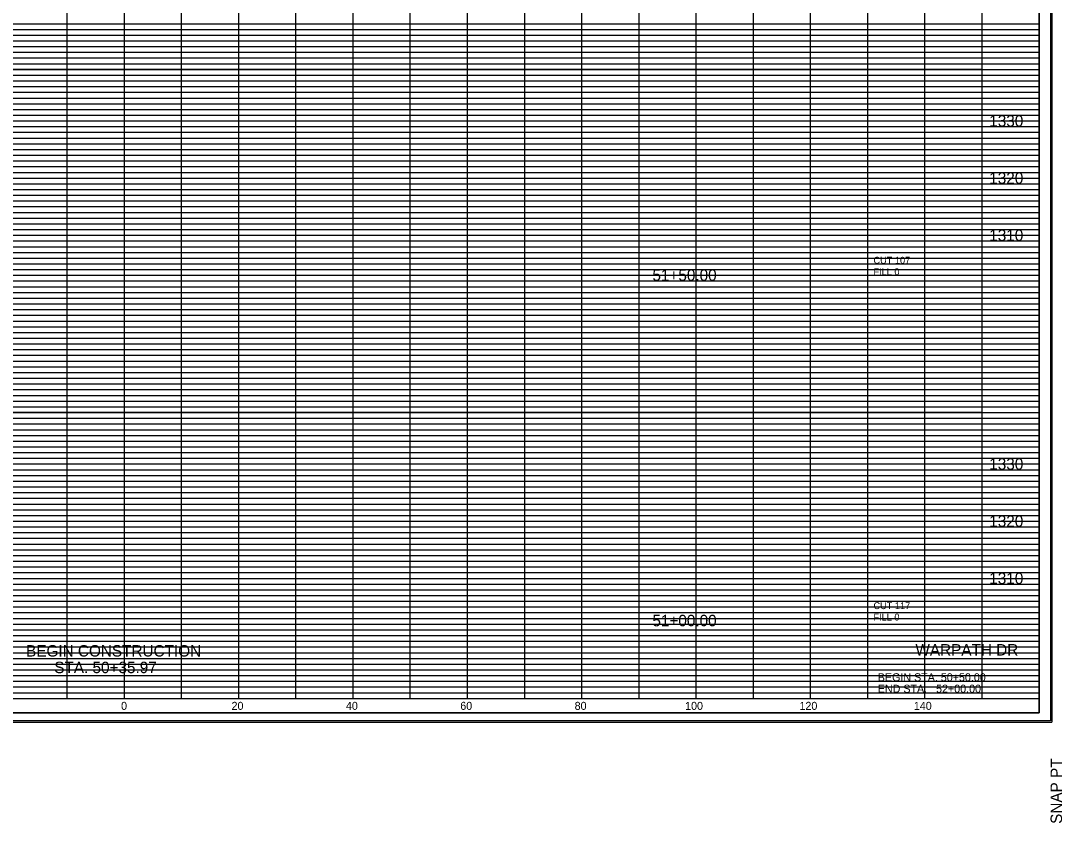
# Model space of a CAD drawing. Extents: x 130 to 1324, y -58 to 2657.
# Drawn here: x 1141.9 to 1324, y 978.2 to 1118.5 of the extents above; entities that cross this region are included whole.
import ezdxf

# ---------------------------------------------------------------- set-up
doc = ezdxf.new("R2010")
doc.units = 0
for name, color, linetype in [('DESIGN - SCRATCH - User 2', 7, 'Continuous'), ('DESIGN - SHEET - Corner Text', 7, 'Continuous'), ('DESIGN - SHEET - Light Grid', 7, 'Continuous'), ('DESIGN - SHEET - Linework', 7, 'Continuous'), ('DESIGN - SHEET - Plot Shape', 7, 'Continuous'), ('DESIGN - TYPICAL - Finished Grade and Subgrade', 7, 'Continuous'), ('DESIGN - TYPICAL - Text', 7, 'Continuous')]:
    doc.layers.add(name, color=color, linetype=linetype)

# ---------------------------------------------------------------- blocks, each defined once
blk = doc.blocks.new('XSTSHT')
at = {"layer": 'DESIGN - SHEET - Light Grid'}
for p, q in [((8, 11.8), (16, 11.8)), ((8, 11.7), (16, 11.7)), ((16, 11.8), (24, 11.8)), ((16, 11.7), (24, 11.7)), ((24, 11.8), (32, 11.8)), ((24, 11.7), (32, 11.7)), ((8, 11.6), (16, 11.6)), ((8, 11.5), (16, 11.5)), ((16, 11.6), (24, 11.6)), ((16, 11.5), (24, 11.5)), ((24, 11.6), (32, 11.6)), ((24, 11.5), (32, 11.5)), ((8, 11.4), (16, 11.4)), ((8, 11.3), (16, 11.3)), ((16, 11.4), (24, 11.4)), ((16, 11.3), (24, 11.3)), ((24, 11.4), (32, 11.4)), ((24, 11.3), (32, 11.3)), ((8, 11.2), (16, 11.2)), ((16, 11.2), (24, 11.2)), ((24, 11.2), (32, 11.2)), ((8, 11.1), (16, 11.1)), ((16, 11.1), (24, 11.1)), ((24, 11.1), (32, 11.1)), ((8, 10.9), (16, 10.9)), ((8, 10.8), (16, 10.8)), ((16, 10.9), (24, 10.9)), ((16, 10.8), (24, 10.8)), ((24, 10.9), (32, 10.9)), ((24, 10.8), (32, 10.8)), ((8, 10.7), (16, 10.7)), ((8, 10.6), (16, 10.6)), ((16, 10.7), (24, 10.7)), ((16, 10.6), (24, 10.6)), ((24, 10.7), (32, 10.7)), ((24, 10.6), (32, 10.6)), ((8, 10.5), (16, 10.5)), ((8, 10.4), (16, 10.4)), ((16, 10.5), (24, 10.5)), ((16, 10.4), (24, 10.4)), ((24, 10.5), (32, 10.5)), ((24, 10.4), (32, 10.4)), ((8, 10.3), (16, 10.3)), ((8, 10.2), (16, 10.2)), ((16, 10.3), (24, 10.3)), ((16, 10.2), (24, 10.2)), ((24, 10.3), (32, 10.3)), ((24, 10.2), (32, 10.2)), ((8, 10.1), (16, 10.1)), ((16, 10.1), (24, 10.1)), ((24, 10.1), (32, 10.1)), ((8, 9.9), (16, 9.9)), ((16, 9.9), (24, 9.9)), ((24, 9.9), (32, 9.9)), ((8, 9.8), (16, 9.8)), ((8, 9.7), (16, 9.7)), ((16, 9.8), (24, 9.8)), ((16, 9.7), (24, 9.7)), ((24, 9.8), (32, 9.8)), ((24, 9.7), (32, 9.7)), ((8, 9.6), (16, 9.6)), ((8, 9.5), (16, 9.5)), ((16, 9.6), (24, 9.6)), ((16, 9.5), (24, 9.5)), ((24, 9.6), (32, 9.6)), ((24, 9.5), (32, 9.5)), ((8, 9.4), (16, 9.4)), ((8, 9.3), (16, 9.3)), ((16, 9.4), (24, 9.4)), ((16, 9.3), (24, 9.3)), ((24, 9.4), (32, 9.4)), ((24, 9.3), (32, 9.3)), ((8, 9.2), (16, 9.2)), ((16, 9.2), (24, 9.2)), ((24, 9.2), (32, 9.2)), ((8, 9.1), (16, 9.1)), ((16, 9.1), (24, 9.1)), ((24, 9.1), (32, 9.1)), ((8, 8.9), (16, 8.9)), ((8, 8.8), (16, 8.8)), ((16, 8.9), (24, 8.9)), ((16, 8.8), (24, 8.8)), ((24, 8.9), (32, 8.9)), ((24, 8.8), (32, 8.8)), ((8, 8.7), (16, 8.7)), ((8, 8.6), (16, 8.6)), ((16, 8.7), (24, 8.7)), ((16, 8.6), (24, 8.6)), ((24, 8.7), (32, 8.7)), ((24, 8.6), (32, 8.6)), ((8, 8.5), (16, 8.5)), ((8, 8.4), (16, 8.4)), ((16, 8.5), (24, 8.5)), ((16, 8.4), (24, 8.4)), ((24, 8.5), (32, 8.5)), ((24, 8.4), (32, 8.4)), ((8, 8.3), (16, 8.3)), ((8, 8.2), (16, 8.2)), ((16, 8.3), (24, 8.3)), ((16, 8.2), (24, 8.2)), ((24, 8.3), (32, 8.3)), ((24, 8.2), (32, 8.2)), ((8, 8.1), (16, 8.1)), ((16, 8.1), (24, 8.1)), ((24, 8.1), (32, 8.1)), ((8, 7.9), (16, 7.9)), ((16, 7.9), (24, 7.9)), ((24, 7.9), (32, 7.9)), ((8, 7.8), (16, 7.8)), ((8, 7.7), (16, 7.7)), ((16, 7.8), (24, 7.8)), ((16, 7.7), (24, 7.7)), ((24, 7.8), (32, 7.8)), ((24, 7.7), (32, 7.7)), ((8, 7.6), (16, 7.6)), ((8, 7.5), (16, 7.5)), ((16, 7.6), (24, 7.6)), ((16, 7.5), (24, 7.5)), ((24, 7.6), (32, 7.6)), ((24, 7.5), (32, 7.5)), ((8, 7.4), (16, 7.4)), ((8, 7.3), (16, 7.3)), ((16, 7.4), (24, 7.4)), ((16, 7.3), (24, 7.3)), ((24, 7.4), (32, 7.4)), ((24, 7.3), (32, 7.3)), ((8, 7.2), (16, 7.2)), ((16, 7.2), (24, 7.2)), ((24, 7.2), (32, 7.2)), ((8, 7.1), (16, 7.1)), ((16, 7.1), (24, 7.1)), ((24, 7.1), (32, 7.1)), ((8, 6.9), (16, 6.9)), ((8, 6.8), (16, 6.8)), ((16, 6.9), (24, 6.9)), ((16, 6.8), (24, 6.8)), ((24, 6.9), (32, 6.9)), ((24, 6.8), (32, 6.8)), ((8, 6.7), (16, 6.7)), ((8, 6.6), (16, 6.6)), ((16, 6.7), (24, 6.7)), ((16, 6.6), (24, 6.6)), ((24, 6.7), (32, 6.7)), ((24, 6.6), (32, 6.6)), ((8, 6.5), (16, 6.5)), ((8, 6.4), (16, 6.4)), ((16, 6.5), (24, 6.5)), ((16, 6.4), (24, 6.4)), ((24, 6.5), (32, 6.5)), ((24, 6.4), (32, 6.4)), ((8, 6.3), (16, 6.3)), ((8, 6.2), (16, 6.2)), ((16, 6.3), (24, 6.3)), ((16, 6.2), (24, 6.2)), ((24, 6.3), (32, 6.3)), ((24, 6.2), (32, 6.2)), ((8, 6.1), (16, 6.1)), ((16, 6.1), (24, 6.1)), ((24, 6.1), (32, 6.1)), ((8, 5.9), (16, 5.9)), ((16, 5.9), (24, 5.9)), ((24, 5.9), (32, 5.9)), ((8, 5.8), (16, 5.8)), ((8, 5.7), (16, 5.7)), ((16, 5.8), (24, 5.8)), ((16, 5.7), (24, 5.7)), ((24, 5.8), (32, 5.8)), ((24, 5.7), (32, 5.7)), ((8, 5.6), (16, 5.6)), ((8, 5.5), (16, 5.5)), ((16, 5.6), (24, 5.6)), ((16, 5.5), (24, 5.5)), ((24, 5.6), (32, 5.6)), ((24, 5.5), (32, 5.5)), ((8, 5.4), (16, 5.4)), ((8, 5.3), (16, 5.3)), ((16, 5.4), (24, 5.4)), ((16, 5.3), (24, 5.3)), ((24, 5.4), (32, 5.4)), ((24, 5.3), (32, 5.3)), ((8, 5.2), (16, 5.2)), ((8, 5.1), (16, 5.1)), ((16, 5.2), (24, 5.2)), ((16, 5.1), (24, 5.1)), ((24, 5.2), (32, 5.2)), ((24, 5.1), (32, 5.1)), ((8, 4.9), (16, 4.9)), ((8, 4.8), (16, 4.8)), ((16, 4.9), (24, 4.9)), ((16, 4.8), (24, 4.8)), ((24, 4.9), (32, 4.9)), ((24, 4.8), (32, 4.8)), ((8, 4.7), (16, 4.7)), ((8, 4.6), (16, 4.6)), ((16, 4.7), (24, 4.7)), ((16, 4.6), (24, 4.6)), ((24, 4.7), (32, 4.7)), ((24, 4.6), (32, 4.6)), ((8, 4.5), (16, 4.5)), ((8, 4.4), (16, 4.4)), ((16, 4.5), (24, 4.5)), ((16, 4.4), (24, 4.4)), ((24, 4.5), (32, 4.5)), ((24, 4.4), (32, 4.4)), ((8, 4.3), (16, 4.3)), ((8, 4.2), (16, 4.2)), ((16, 4.3), (24, 4.3)), ((16, 4.2), (24, 4.2)), ((24, 4.3), (32, 4.3)), ((24, 4.2), (32, 4.2)), ((8, 4.1), (16, 4.1)), ((16, 4.1), (24, 4.1)), ((24, 4.1), (32, 4.1)), ((8, 3.9), (16, 3.9)), ((16, 3.9), (24, 3.9)), ((24, 3.9), (32, 3.9)), ((8, 3.8), (16, 3.8)), ((8, 3.7), (16, 3.7)), ((16, 3.8), (24, 3.8)), ((16, 3.7), (24, 3.7)), ((24, 3.8), (32, 3.8)), ((24, 3.7), (32, 3.7)), ((8, 3.6), (16, 3.6)), ((8, 3.5), (16, 3.5)), ((16, 3.6), (24, 3.6)), ((16, 3.5), (24, 3.5)), ((24, 3.6), (32, 3.6)), ((24, 3.5), (32, 3.5)), ((8, 3.4), (16, 3.4)), ((8, 3.3), (16, 3.3)), ((16, 3.4), (24, 3.4)), ((16, 3.3), (24, 3.3)), ((24, 3.4), (32, 3.4)), ((24, 3.3), (32, 3.3)), ((8, 3.2), (16, 3.2)), ((8, 3.1), (16, 3.1)), ((16, 3.2), (24, 3.2)), ((16, 3.1), (24, 3.1)), ((24, 3.2), (32, 3.2)), ((24, 3.1), (32, 3.1)), ((8, 2.9), (16, 2.9)), ((8, 2.8), (16, 2.8)), ((16, 2.9), (24, 2.9)), ((16, 2.8), (24, 2.8)), ((24, 2.9), (32, 2.9)), ((24, 2.8), (32, 2.8)), ((8, 2.7), (16, 2.7)), ((8, 2.6), (16, 2.6)), ((16, 2.7), (24, 2.7)), ((16, 2.6), (24, 2.6)), ((24, 2.7), (32, 2.7)), ((24, 2.6), (32, 2.6)), ((8, 2.5), (16, 2.5)), ((8, 2.4), (16, 2.4)), ((16, 2.5), (24, 2.5)), ((16, 2.4), (24, 2.4)), ((24, 2.5), (32, 2.5)), ((24, 2.4), (32, 2.4)), ((8, 2.3), (16, 2.3)), ((8, 2.2), (16, 2.2)), ((16, 2.3), (24, 2.3)), ((16, 2.2), (24, 2.2)), ((24, 2.3), (32, 2.3)), ((24, 2.2), (32, 2.2)), ((8, 2.1), (16, 2.1)), ((16, 2.1), (24, 2.1)), ((24, 2.1), (32, 2.1)), ((8, 1.9), (16, 1.9)), ((16, 1.9), (24, 1.9)), ((24, 1.9), (32, 1.9)), ((8, 1.8), (16, 1.8)), ((8, 1.7), (16, 1.7)), ((16, 1.8), (24, 1.8)), ((16, 1.7), (24, 1.7)), ((24, 1.8), (32, 1.8)), ((24, 1.7), (32, 1.7)), ((8, 1.6), (16, 1.6)), ((8, 1.5), (16, 1.5)), ((16, 1.6), (24, 1.6)), ((16, 1.5), (24, 1.5)), ((24, 1.6), (32, 1.6)), ((24, 1.5), (32, 1.5)), ((8, 1.4), (16, 1.4)), ((8, 1.3), (16, 1.3)), ((16, 1.4), (24, 1.4)), ((16, 1.3), (24, 1.3)), ((24, 1.4), (32, 1.4)), ((24, 1.3), (32, 1.3)), ((8, 1.2), (16, 1.2)), ((8, 1.1), (16, 1.1)), ((16, 1.2), (24, 1.2)), ((16, 1.1), (24, 1.1)), ((24, 1.2), (32, 1.2)), ((24, 1.1), (32, 1.1)), ((8, 0.9), (16, 0.9)), ((8, 0.8), (16, 0.8)), ((16, 0.9), (24, 0.9)), ((16, 0.8), (24, 0.8)), ((24, 0.9), (32, 0.9)), ((24, 0.8), (32, 0.8)), ((8, 0.7), (16, 0.7)), ((8, 0.6), (16, 0.6)), ((16, 0.7), (24, 0.7)), ((16, 0.6), (24, 0.6)), ((24, 0.7), (32, 0.7)), ((24, 0.6), (32, 0.6)), ((8, 0.5), (16, 0.5)), ((8, 0.4), (16, 0.4)), ((16, 0.5), (24, 0.5)), ((16, 0.4), (24, 0.4)), ((24, 0.5), (32, 0.5)), ((24, 0.4), (32, 0.4)), ((8, 0.3), (16, 0.3)), ((8, 0.2), (16, 0.2)), ((16, 0.3), (24, 0.3)), ((16, 0.2), (24, 0.2)), ((24, 0.3), (32, 0.3)), ((24, 0.2), (32, 0.2)), ((8, 0.1), (16, 0.1)), ((16, 0.1), (24, 0.1)), ((24, 0.1), (32, 0.1))]:
    blk.add_line(p, q, dxfattribs=at)
at = {"layer": 'DESIGN - SHEET - Linework'}
for p, q in [((32.217, 21.414), (32.217, -0.414)), ((15, 0), (15, 21)), ((16, 0), (16, 21)), ((17, 0), (17, 21)), ((18, 0), (18, 21)), ((19, 0), (19, 21)), ((20, 0), (20, 21)), ((21, 0), (21, 21)), ((22, 0), (22, 21)), ((23, 0), (23, 21)), ((24, 0), (24, 21)), ((25, 0), (25, 21)), ((26, 0), (26, 21)), ((27, 0), (27, 21)), ((28, 0), (28, 20)), ((29, 0), (29, 20)), ((30, 0), (30, 20)), ((31, 0), (31, 20)), ((0, 11), (32, 11)), ((0, 10), (32, 10)), ((0, 9), (32, 9)), ((0, 8), (32, 8)), ((0, 7), (32, 7)), ((0, 6), (32, 6)), ((0, 5), (32, 5)), ((0, 4), (32, 4)), ((0, 3), (32, 3)), ((0, 2), (32, 2)), ((0, 1), (32, 1)), ((-1.823, -0.414), (32.217, -0.414))]:
    blk.add_line(p, q, dxfattribs=at)
blk.add_lwpolyline([(0, 21), (0, 0), (32, 0), (32, 21), (0, 21)], dxfattribs=at)
at = {"layer": 'DESIGN - SHEET - Plot Shape'}
for points in [[(-1.803, 21.394), (32.197, 21.394), (32.197, -0.394), (-1.803, -0.394)], [(-0.85, 21), (32, 21), (32, -0.25), (-0.85, -0.25)]]:
    blk.add_lwpolyline(points, close=True, dxfattribs=at)
at = {"layer": 'DESIGN - SHEET - Corner Text'}
blk.add_text('SNAP PT  ', height=0.2, rotation=90, dxfattribs=at).set_placement((32.397, -2.194))

msp = doc.modelspace()

# ---------------------------------------------------------------- linework, layer by layer
at = {"layer": 'DESIGN - SCRATCH - User 2'}
for points in [[(1010, 1070), (1310, 1070), (1310, 1110), (1010, 1110)], [(1010, 1010), (1310, 1010), (1310, 1050), (1010, 1050)]]:
    msp.add_lwpolyline(points, close=True, dxfattribs=at)
at = {"layer": 'DESIGN - SHEET - Plot Shape'}
msp.add_lwpolyline([(991.5, 997.5), (1320, 997.5), (1320, 1210), (991.5, 1210)], close=True, dxfattribs=at)

# ---------------------------------------------------------------- block references
at = {"layer": 'DESIGN - TYPICAL - Finished Grade and Subgrade', "xscale": 10, "yscale": 10}
msp.add_blockref('XSTSHT', (1000, 1000), dxfattribs=at)

# ---------------------------------------------------------------- texts
at = {"layer": 'DESIGN - SHEET - Corner Text'}
for s, height, p in [('1330', 2, (1311.25, 1100)), ('1320', 2, (1311.25, 1090)), ('1310', 2, (1311.25, 1080)), ('51+50.00', 2, (1252.34, 1073.03)), ('1330', 2, (1311.25, 1040)), ('1320', 2, (1311.25, 1030)), ('1310', 2, (1311.25, 1020)), ('51+00.00', 2, (1252.34, 1012.62)), ('WARPATH DR', 2, (1298.34, 1007.5)), ('BEGIN STA. 50+50.00', 1.4, (1291.75, 1003)), ('END STA.   52+00.00', 1.4, (1291.75, 1001)), ('0', 1.4, (1159.42, 998)), ('0', 1.4, (1159.42, 998)), ('20', 1.4, (1178.74, 998)), ('40', 1.4, (1198.74, 998)), ('60', 1.4, (1218.74, 998)), ('80', 1.4, (1238.74, 998)), ('100', 1.4, (1258.06, 998)), ('120', 1.4, (1278.06, 998)), ('140', 1.4, (1298.06, 998))]:
    msp.add_text(s, height=height, dxfattribs=at).set_placement(p)
at = {"layer": 'DESIGN - TYPICAL - Text'}
for s, height, p in [('CUT 107', 1.2, (1291, 1076.03)), ('FILL 0', 1.2, (1291, 1074.03)), ('CUT 117', 1.2, (1291, 1015.62)), ('FILL 0', 1.2, (1291, 1013.62)), ('BEGIN CONSTRUCTION', 2, (1142.81, 1007.32)), ('STA. 50+35.97', 2, (1147.74, 1004.42))]:
    msp.add_text(s, height=height, dxfattribs=at).set_placement(p)

doc.saveas('drawing.dxf')
